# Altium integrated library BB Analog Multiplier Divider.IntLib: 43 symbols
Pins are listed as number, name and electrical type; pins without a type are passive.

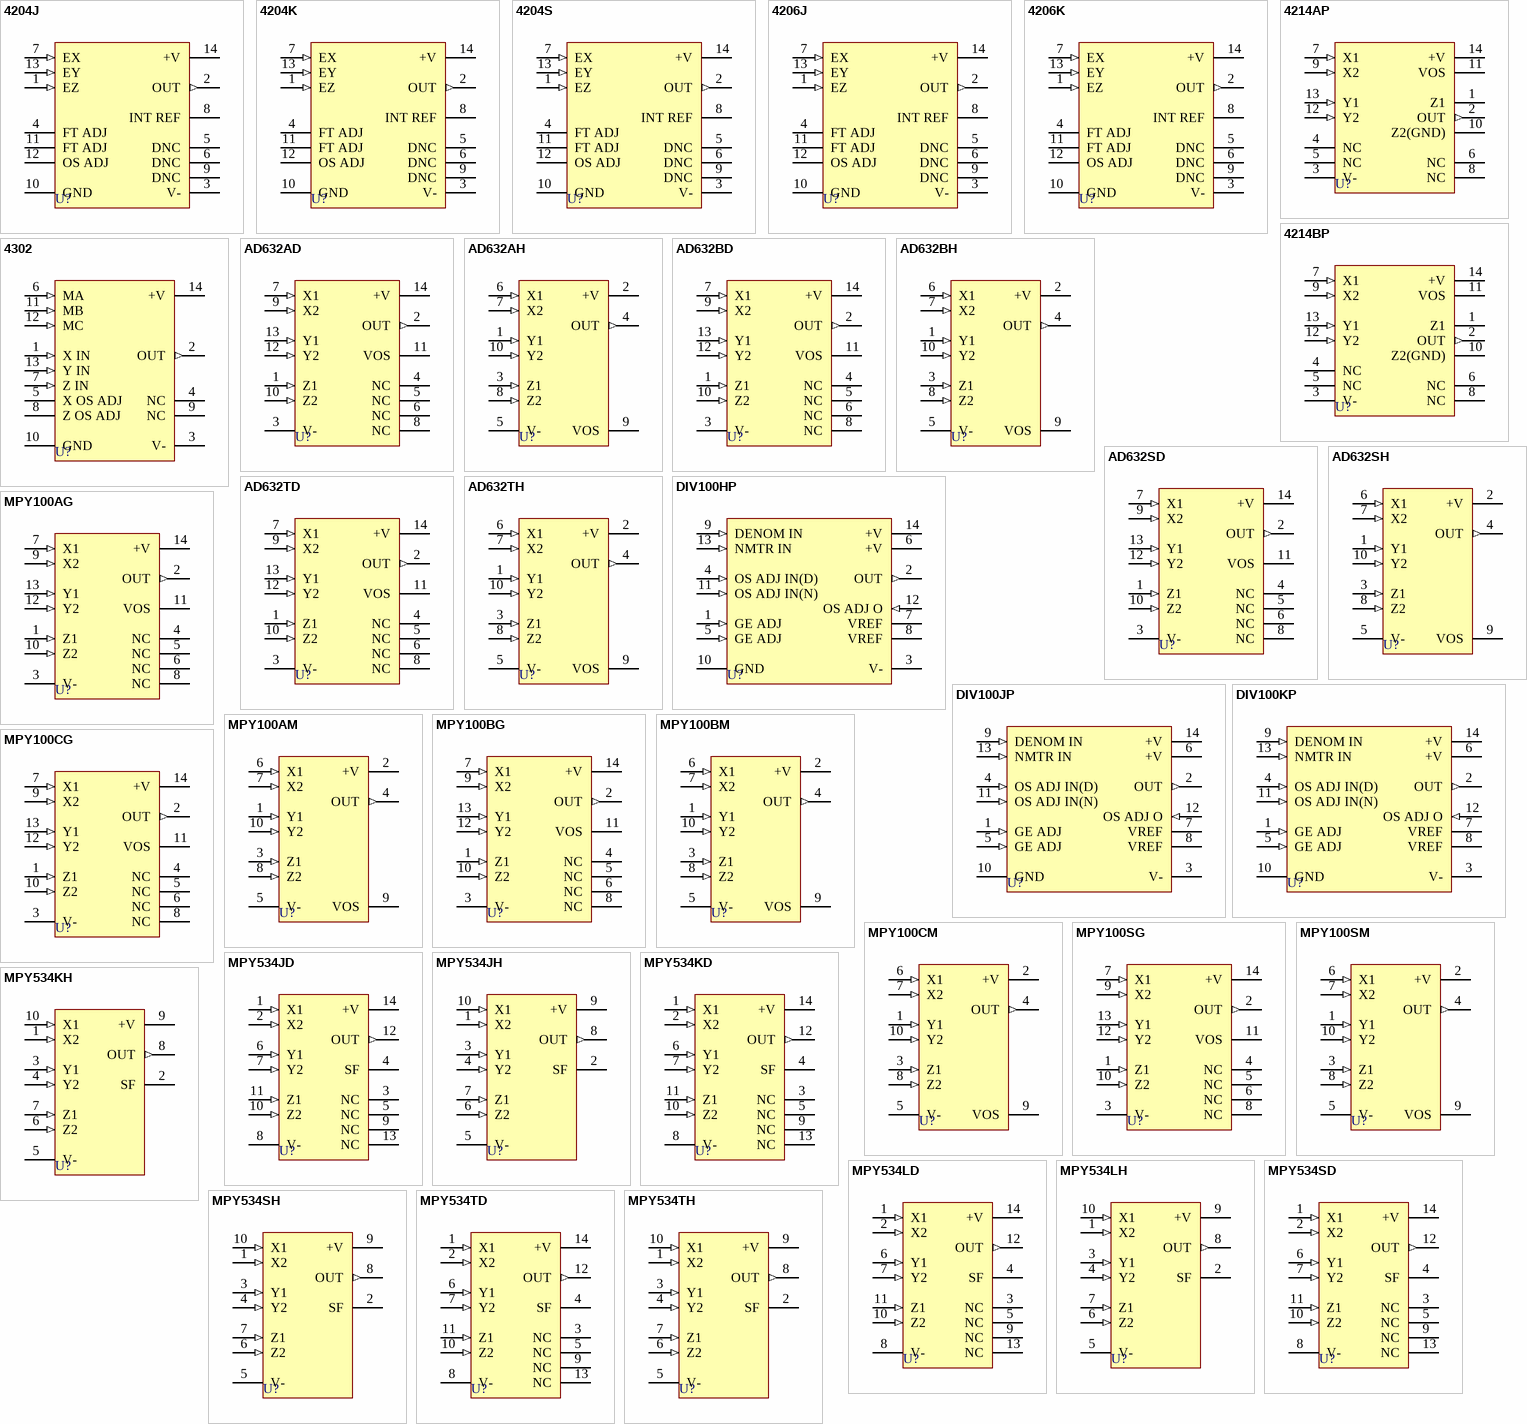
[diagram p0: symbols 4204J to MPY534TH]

## 4204J
designator U?
Analog Multiplier-Divider; Note: Make no connection to pins 5, 6 and 9
footprint ZZ107 (DIP; 14 Round Pins; Row Space 7.62 mm; Pitch 2.54 mm)
pins: 1 EZ (in), 2 OUT (out), 3 V- (power), 4 FT ADJ, 5 DNC, 6 DNC, 7 EX (in), 8 INT REF, 9 DNC, 10 GND (power), 11 FT ADJ, 12 OS ADJ, 13 EY (in), 14 +V (power)

## 4204K
designator U?
Analog Multiplier-Divider; Note: Make no connection to pins 5, 6 and 9
footprint ZZ107 (DIP; 14 Round Pins; Row Space 7.62 mm; Pitch 2.54 mm)
pins: 1 EZ (in), 2 OUT (out), 3 V- (power), 4 FT ADJ, 5 DNC, 6 DNC, 7 EX (in), 8 INT REF, 9 DNC, 10 GND (power), 11 FT ADJ, 12 OS ADJ, 13 EY (in), 14 +V (power)

## 4204S
designator U?
Analog Multiplier-Divider; Note: Make no connection to pins 5, 6 and 9
footprint ZZ107 (DIP; 14 Round Pins; Row Space 7.62 mm; Pitch 2.54 mm)
pins: 1 EZ (in), 2 OUT (out), 3 V- (power), 4 FT ADJ, 5 DNC, 6 DNC, 7 EX (in), 8 INT REF, 9 DNC, 10 GND (power), 11 FT ADJ, 12 OS ADJ, 13 EY (in), 14 +V (power)

## 4206J
designator U?
Analog Multiplier-Divider; Note: Make no connection to pins 5, 6 and 9
footprint ZZ003 (DIP; 14 Round Pins; Row Space 7.62 mm; Pitch 2.54 mm)
pins: 1 EZ (in), 2 OUT (out), 3 V- (power), 4 FT ADJ, 5 DNC, 6 DNC, 7 EX (in), 8 INT REF, 9 DNC, 10 GND (power), 11 FT ADJ, 12 OS ADJ, 13 EY (in), 14 +V (power)

## 4206K
designator U?
Analog Multiplier-Divider; Note: Make no connection to pins 5, 6 and 9
footprint ZZ003 (DIP; 14 Round Pins; Row Space 7.62 mm; Pitch 2.54 mm)
pins: 1 EZ (in), 2 OUT (out), 3 V- (power), 4 FT ADJ, 5 DNC, 6 DNC, 7 EX (in), 8 INT REF, 9 DNC, 10 GND (power), 11 FT ADJ, 12 OS ADJ, 13 EY (in), 14 +V (power)

## 4214AP
designator U?
Multiplier-Divider; Note: Pins 4, 5, 6 and 8 are No internal Connection (NC) pins.
footprint ZZ003 (DIP; 14 Round Pins; Row Space 7.62 mm; Pitch 2.54 mm)
pins: 1 Z1, 2 OUT (out), 3 V- (power), 4 NC, 5 NC, 6 NC, 7 X1 (in), 8 NC, 9 X2 (in), 10 Z2(GND), 11 VOS, 12 Y2 (in), 13 Y1 (in), 14 +V (power)

## 4214BP
designator U?
Multiplier-Divider; Note: Pins 4, 5, 6 and 8 are No internal Connection (NC) pins.
footprint ZZ003 (DIP; 14 Round Pins; Row Space 7.62 mm; Pitch 2.54 mm)
pins: 1 Z1, 2 OUT (out), 3 V- (power), 4 NC, 5 NC, 6 NC, 7 X1 (in), 8 NC, 9 X2 (in), 10 Z2(GND), 11 VOS, 12 Y2 (in), 13 Y1 (in), 14 +V (power)

## 4302
designator U?
Low-Cost Multifunction Converter; Note: Pins 4 and 9 are No internal Connection (NC) pins.
footprint ZZ003 (DIP; 14 Round Pins; Row Space 7.62 mm; Pitch 2.54 mm)
pins: 1 X IN (in), 2 OUT (out), 3 V- (power), 4 NC, 5 X OS ADJ, 6 MA (in), 7 Z IN (in), 8 Z OS ADJ, 9 NC, 10 GND (power), 11 MB (in), 12 MC (in), 13 Y IN (in), 14 +V (power)

## AD632AD
designator U?
Precision Analog Multiplier; Note: Pins 4,5,6 and 8 are No internal Connection (NC) pins.
footprint 137 (DIP; 14 Leads; Row Spacing 7.62 mm; Pitch 2.54 mm)
3D model 137 (DIP; 14 Leads; Row Spacing 7.62 mm; Pitch 2.54 mm)
pins: 1 Z1 (in), 2 OUT (out), 3 V- (power), 4 NC, 5 NC, 6 NC, 7 X1 (in), 8 NC, 9 X2 (in), 10 Z2 (in), 11 VOS, 12 Y2 (in), 13 Y1 (in), 14 +V (power)

## AD632AH
designator U?
Precision Analog Multiplier
footprint ZZ007 (Can; 10 Leads; Pin Circle Dia. 5.84 mm (TO-100); Lead Dia. 0.53 mm (max))
pins: 1 Y1 (in), 2 +V (power), 3 Z1 (in), 4 OUT (out), 5 V- (power), 6 X1 (in), 7 X2 (in), 8 Z2 (in), 9 VOS, 10 Y2 (in)

## AD632BD
designator U?
Precision Analog Multiplier; Note: Pins 4,5,6 and 8 are No internal Connection (NC) pins.
footprint 137 (DIP; 14 Leads; Row Spacing 7.62 mm; Pitch 2.54 mm)
3D model 137 (DIP; 14 Leads; Row Spacing 7.62 mm; Pitch 2.54 mm)
pins: 1 Z1 (in), 2 OUT (out), 3 V- (power), 4 NC, 5 NC, 6 NC, 7 X1 (in), 8 NC, 9 X2 (in), 10 Z2 (in), 11 VOS, 12 Y2 (in), 13 Y1 (in), 14 +V (power)

## AD632BH
designator U?
Precision Analog Multiplier
footprint ZZ007 (Can; 10 Leads; Pin Circle Dia. 5.84 mm (TO-100); Lead Dia. 0.53 mm (max))
pins: 1 Y1 (in), 2 +V (power), 3 Z1 (in), 4 OUT (out), 5 V- (power), 6 X1 (in), 7 X2 (in), 8 Z2 (in), 9 VOS, 10 Y2 (in)

## AD632SD
designator U?
Precision Analog Multiplier; Note: Pins 4,5,6 and 8 are No internal Connection (NC) pins.
footprint 137 (DIP; 14 Leads; Row Spacing 7.62 mm; Pitch 2.54 mm)
3D model 137 (DIP; 14 Leads; Row Spacing 7.62 mm; Pitch 2.54 mm)
pins: 1 Z1 (in), 2 OUT (out), 3 V- (power), 4 NC, 5 NC, 6 NC, 7 X1 (in), 8 NC, 9 X2 (in), 10 Z2 (in), 11 VOS, 12 Y2 (in), 13 Y1 (in), 14 +V (power)

## AD632SH
designator U?
Precision Analog Multiplier
footprint ZZ007 (Can; 10 Leads; Pin Circle Dia. 5.84 mm (TO-100); Lead Dia. 0.53 mm (max))
pins: 1 Y1 (in), 2 +V (power), 3 Z1 (in), 4 OUT (out), 5 V- (power), 6 X1 (in), 7 X2 (in), 8 Z2 (in), 9 VOS, 10 Y2 (in)

## AD632TD
designator U?
Precision Analog Multiplier; Note: Pins 4,5,6 and 8 are No internal Connection (NC) pins.
footprint 137 (DIP; 14 Leads; Row Spacing 7.62 mm; Pitch 2.54 mm)
3D model 137 (DIP; 14 Leads; Row Spacing 7.62 mm; Pitch 2.54 mm)
pins: 1 Z1 (in), 2 OUT (out), 3 V- (power), 4 NC, 5 NC, 6 NC, 7 X1 (in), 8 NC, 9 X2 (in), 10 Z2 (in), 11 VOS, 12 Y2 (in), 13 Y1 (in), 14 +V (power)

## AD632TH
designator U?
Precision Analog Multiplier
footprint ZZ007 (Can; 10 Leads; Pin Circle Dia. 5.84 mm (TO-100); Lead Dia. 0.53 mm (max))
pins: 1 Y1 (in), 2 +V (power), 3 Z1 (in), 4 OUT (out), 5 V- (power), 6 X1 (in), 7 X2 (in), 8 Z2 (in), 9 VOS, 10 Y2 (in)

## DIV100HP
designator U?
Analog Divider
footprint ZZ105 (DIP; 14 Round Pins; Row Space 7.62 mm; Pitch 2.54 mm)
pins: 1 GE ADJ (in), 2 OUT (out), 3 V- (power), 4 OS ADJ IN(D) (in), 5 GE ADJ (in), 6 +V (power), 7 VREF, 8 VREF, 9 DENOM IN (in), 10 GND (power), 11 OS ADJ IN(N) (in), 12 OS ADJ O (in), 13 NMTR IN (in), 14 +V (power)

## DIV100JP
designator U?
Analog Divider
footprint ZZ105 (DIP; 14 Round Pins; Row Space 7.62 mm; Pitch 2.54 mm)
pins: 1 GE ADJ (in), 2 OUT (out), 3 V- (power), 4 OS ADJ IN(D) (in), 5 GE ADJ (in), 6 +V (power), 7 VREF, 8 VREF, 9 DENOM IN (in), 10 GND (power), 11 OS ADJ IN(N) (in), 12 OS ADJ O (in), 13 NMTR IN (in), 14 +V (power)

## DIV100KP
designator U?
Analog Divider
footprint ZZ105 (DIP; 14 Round Pins; Row Space 7.62 mm; Pitch 2.54 mm)
pins: 1 GE ADJ (in), 2 OUT (out), 3 V- (power), 4 OS ADJ IN(D) (in), 5 GE ADJ (in), 6 +V (power), 7 VREF, 8 VREF, 9 DENOM IN (in), 10 GND (power), 11 OS ADJ IN(N) (in), 12 OS ADJ O (in), 13 NMTR IN (in), 14 +V (power)

## MPY100AG
designator U?
Multiplier-Divider; Note: Pins 4,5,6 and 8 are No internal Connection (NC) pins.
footprint 169F (DIP; 14 Leads; Row Spacing 7.62 mm; Pitch 2.54 mm)
3D model 010G (DIP; 14 Leads; Row Spacing 7.62 mm; Pitch 2.54 mm)
pins: 1 Z1 (in), 2 OUT (out), 3 V- (power), 4 NC, 5 NC, 6 NC, 7 X1 (in), 8 NC, 9 X2 (in), 10 Z2 (in), 11 VOS, 12 Y2 (in), 13 Y1 (in), 14 +V (power)

## MPY100AM
designator U?
Multiplier-Divider
footprint ZZ007 (Can; 10 Leads; Pin Circle Dia. 5.84 mm (TO-100); Lead Dia. 0.53 mm (max))
pins: 1 Y1 (in), 2 +V (power), 3 Z1 (in), 4 OUT (out), 5 V- (power), 6 X1 (in), 7 X2 (in), 8 Z2 (in), 9 VOS, 10 Y2 (in)

## MPY100BG
designator U?
Multiplier-Divider; Note: Pins 4,5,6 and 8 are No internal Connection (NC) pins.
footprint 169F (DIP; 14 Leads; Row Spacing 7.62 mm; Pitch 2.54 mm)
3D model 010G (DIP; 14 Leads; Row Spacing 7.62 mm; Pitch 2.54 mm)
pins: 1 Z1 (in), 2 OUT (out), 3 V- (power), 4 NC, 5 NC, 6 NC, 7 X1 (in), 8 NC, 9 X2 (in), 10 Z2 (in), 11 VOS, 12 Y2 (in), 13 Y1 (in), 14 +V (power)

## MPY100BM
designator U?
Multiplier-Divider
footprint ZZ007 (Can; 10 Leads; Pin Circle Dia. 5.84 mm (TO-100); Lead Dia. 0.53 mm (max))
pins: 1 Y1 (in), 2 +V (power), 3 Z1 (in), 4 OUT (out), 5 V- (power), 6 X1 (in), 7 X2 (in), 8 Z2 (in), 9 VOS, 10 Y2 (in)

## MPY100CG
designator U?
Multiplier-Divider; Note: Pins 4,5,6 and 8 are No internal Connection (NC) pins.
footprint 169F (DIP; 14 Leads; Row Spacing 7.62 mm; Pitch 2.54 mm)
3D model 010G (DIP; 14 Leads; Row Spacing 7.62 mm; Pitch 2.54 mm)
pins: 1 Z1 (in), 2 OUT (out), 3 V- (power), 4 NC, 5 NC, 6 NC, 7 X1 (in), 8 NC, 9 X2 (in), 10 Z2 (in), 11 VOS, 12 Y2 (in), 13 Y1 (in), 14 +V (power)

## MPY100CM
designator U?
Multiplier-Divider
footprint ZZ007 (Can; 10 Leads; Pin Circle Dia. 5.84 mm (TO-100); Lead Dia. 0.53 mm (max))
pins: 1 Y1 (in), 2 +V (power), 3 Z1 (in), 4 OUT (out), 5 V- (power), 6 X1 (in), 7 X2 (in), 8 Z2 (in), 9 VOS, 10 Y2 (in)

## MPY100SG
designator U?
Multiplier-Divider; Note: Pins 4,5,6 and 8 are No internal Connection (NC) pins.
footprint 169F (DIP; 14 Leads; Row Spacing 7.62 mm; Pitch 2.54 mm)
3D model 010G (DIP; 14 Leads; Row Spacing 7.62 mm; Pitch 2.54 mm)
pins: 1 Z1 (in), 2 OUT (out), 3 V- (power), 4 NC, 5 NC, 6 NC, 7 X1 (in), 8 NC, 9 X2 (in), 10 Z2 (in), 11 VOS, 12 Y2 (in), 13 Y1 (in), 14 +V (power)

## MPY100SM
designator U?
Multiplier-Divider
footprint ZZ007 (Can; 10 Leads; Pin Circle Dia. 5.84 mm (TO-100); Lead Dia. 0.53 mm (max))
pins: 1 Y1 (in), 2 +V (power), 3 Z1 (in), 4 OUT (out), 5 V- (power), 6 X1 (in), 7 X2 (in), 8 Z2 (in), 9 VOS, 10 Y2 (in)

## MPY534JD
designator U?
Precision Analog Multiplier; Note: Pins 3,5,9 and 13 are No internal Connection (NC) pins.
footprint 169F (DIP; 14 Leads; Row Spacing 7.62 mm; Pitch 2.54 mm)
3D model 010G (DIP; 14 Leads; Row Spacing 7.62 mm; Pitch 2.54 mm)
pins: 1 X1 (in), 2 X2 (in), 3 NC, 4 SF, 5 NC, 6 Y1 (in), 7 Y2 (in), 8 V- (power), 9 NC, 10 Z2 (in), 11 Z1 (in), 12 OUT (out), 13 NC, 14 +V (power)

## MPY534JH
designator U?
Precision Analog Multiplier
footprint ZZ007 (Can; 10 Leads; Pin Circle Dia. 5.84 mm (TO-100); Lead Dia. 0.53 mm (max))
pins: 1 X2 (in), 2 SF, 3 Y1 (in), 4 Y2 (in), 5 V- (power), 6 Z2 (in), 7 Z1 (in), 8 OUT (out), 9 +V (power), 10 X1 (in)

## MPY534KD
designator U?
Precision Analog Multiplier; Note: Pins 3,5,9 and 13 are No internal Connection (NC) pins.
footprint 169F (DIP; 14 Leads; Row Spacing 7.62 mm; Pitch 2.54 mm)
3D model 010G (DIP; 14 Leads; Row Spacing 7.62 mm; Pitch 2.54 mm)
pins: 1 X1 (in), 2 X2 (in), 3 NC, 4 SF, 5 NC, 6 Y1 (in), 7 Y2 (in), 8 V- (power), 9 NC, 10 Z2 (in), 11 Z1 (in), 12 OUT (out), 13 NC, 14 +V (power)

## MPY534KH
designator U?
Precision Analog Multiplier
footprint ZZ007 (Can; 10 Leads; Pin Circle Dia. 5.84 mm (TO-100); Lead Dia. 0.53 mm (max))
pins: 1 X2 (in), 2 SF, 3 Y1 (in), 4 Y2 (in), 5 V- (power), 6 Z2 (in), 7 Z1 (in), 8 OUT (out), 9 +V (power), 10 X1 (in)

## MPY534LD
designator U?
Precision Analog Multiplier; Note: Pins 3,5,9 and 13 are No internal Connection (NC) pins.
footprint 169F (DIP; 14 Leads; Row Spacing 7.62 mm; Pitch 2.54 mm)
3D model 010G (DIP; 14 Leads; Row Spacing 7.62 mm; Pitch 2.54 mm)
pins: 1 X1 (in), 2 X2 (in), 3 NC, 4 SF, 5 NC, 6 Y1 (in), 7 Y2 (in), 8 V- (power), 9 NC, 10 Z2 (in), 11 Z1 (in), 12 OUT (out), 13 NC, 14 +V (power)

## MPY534LH
designator U?
Precision Analog Multiplier
footprint ZZ007 (Can; 10 Leads; Pin Circle Dia. 5.84 mm (TO-100); Lead Dia. 0.53 mm (max))
pins: 1 X2 (in), 2 SF, 3 Y1 (in), 4 Y2 (in), 5 V- (power), 6 Z2 (in), 7 Z1 (in), 8 OUT (out), 9 +V (power), 10 X1 (in)

## MPY534SD
designator U?
Precision Analog Multiplier; Note: Pins 3,5,9 and 13 are No internal Connection (NC) pins.
footprint 169F (DIP; 14 Leads; Row Spacing 7.62 mm; Pitch 2.54 mm)
3D model 010G (DIP; 14 Leads; Row Spacing 7.62 mm; Pitch 2.54 mm)
pins: 1 X1 (in), 2 X2 (in), 3 NC, 4 SF, 5 NC, 6 Y1 (in), 7 Y2 (in), 8 V- (power), 9 NC, 10 Z2 (in), 11 Z1 (in), 12 OUT (out), 13 NC, 14 +V (power)

## MPY534SH
designator U?
Precision Analog Multiplier
footprint ZZ007 (Can; 10 Leads; Pin Circle Dia. 5.84 mm (TO-100); Lead Dia. 0.53 mm (max))
pins: 1 X2 (in), 2 SF, 3 Y1 (in), 4 Y2 (in), 5 V- (power), 6 Z2 (in), 7 Z1 (in), 8 OUT (out), 9 +V (power), 10 X1 (in)

## MPY534TD
designator U?
Precision Analog Multiplier; Note: Pins 3,5,9 and 13 are No internal Connection (NC) pins.
footprint 169F (DIP; 14 Leads; Row Spacing 7.62 mm; Pitch 2.54 mm)
3D model 010G (DIP; 14 Leads; Row Spacing 7.62 mm; Pitch 2.54 mm)
pins: 1 X1 (in), 2 X2 (in), 3 NC, 4 SF, 5 NC, 6 Y1 (in), 7 Y2 (in), 8 V- (power), 9 NC, 10 Z2 (in), 11 Z1 (in), 12 OUT (out), 13 NC, 14 +V (power)

## MPY534TH
designator U?
Precision Analog Multiplier
footprint ZZ007 (Can; 10 Leads; Pin Circle Dia. 5.84 mm (TO-100); Lead Dia. 0.53 mm (max))
pins: 1 X2 (in), 2 SF, 3 Y1 (in), 4 Y2 (in), 5 V- (power), 6 Z2 (in), 7 Z1 (in), 8 OUT (out), 9 +V (power), 10 X1 (in)

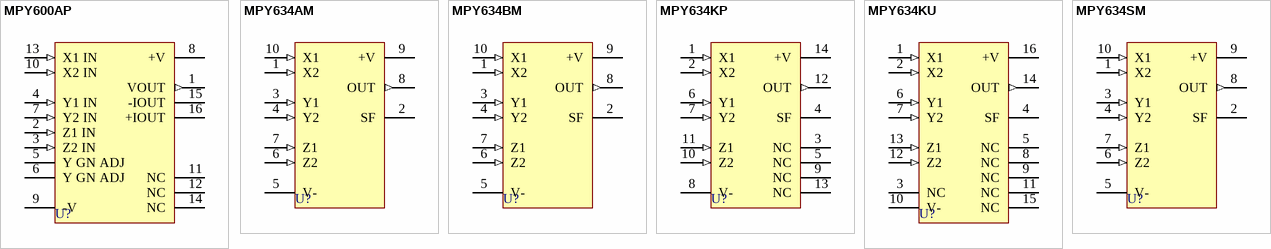
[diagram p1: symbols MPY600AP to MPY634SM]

## MPY600AP
designator U?
Wide-Bandwidth Signal Multiplier; Note: Pins 11, 12 and 14 are No internal Connection (NC) pins.
footprint ZZ180 (DIP, Plastic; 16 Leads; Row Spacing 7.62 mm; Pitch 2.54 mm)
3D model ZZ180 (DIP, Plastic; 16 Leads; Row Spacing 7.62 mm; Pitch 2.54 mm)
pins: 1 VOUT (out), 2 Z1 IN (in), 3 Z2 IN (in), 4 Y1 IN (in), 5 Y GN ADJ, 6 Y GN ADJ, 7 Y2 IN (in), 8 +V (power), 9 -V (power), 10 X2 IN (in), 11 NC, 12 NC, 13 X1 IN (in), 14 NC, 15 -IOUT, 16 +IOUT

## MPY634AM
designator U?
Wide-Bandwidth Precision Analog Multiplier
footprint ZZ007 (Can; 10 Leads; Pin Circle Dia. 5.84 mm (TO-100); Lead Dia. 0.53 mm (max))
pins: 1 X2 (in), 2 SF, 3 Y1 (in), 4 Y2 (in), 5 V- (power), 6 Z2 (in), 7 Z1 (in), 8 OUT (out), 9 +V (power), 10 X1 (in)

## MPY634BM
designator U?
Wide-Bandwidth Precision Analog Multiplier
footprint ZZ007 (Can; 10 Leads; Pin Circle Dia. 5.84 mm (TO-100); Lead Dia. 0.53 mm (max))
pins: 1 X2 (in), 2 SF, 3 Y1 (in), 4 Y2 (in), 5 V- (power), 6 Z2 (in), 7 Z1 (in), 8 OUT (out), 9 +V (power), 10 X1 (in)

## MPY634KP
designator U?
Wide-Bandwidth Precision Analog Multiplier; Note: Pins 3,5,9 and 13 are No internal Connection (NC) pins.
footprint 010G (DIP; 14 Leads; Row Spacing 7.62 mm; Pitch 2.54 mm)
3D model 010G (DIP; 14 Leads; Row Spacing 7.62 mm; Pitch 2.54 mm)
pins: 1 X1 (in), 2 X2 (in), 3 NC, 4 SF, 5 NC, 6 Y1 (in), 7 Y2 (in), 8 V- (power), 9 NC, 10 Z2 (in), 11 Z1 (in), 12 OUT (out), 13 NC, 14 +V (power)

## MPY634KU
designator U?
Wide-Bandwidth Precision Analog Multiplier; Note: Pins 3,5,8,9,11 and 15 are No internal Connection (NC) pins.
footprint 211F_N (SOIC, 16-Leads, Body 10.3x7.5mm, Pitch 1.27mm, IPC Medium Density)
footprint 211F_L (SOIC, 16-Leads, Body 10.3x7.5mm, Pitch 1.27mm, IPC High Density)
footprint 211F_M (SOIC, 16-Leads, Body 10.3x7.5mm, Pitch 1.27mm, IPC Low Density)
3D model SOIC16 (16-Pin Small Outline Integrated Circuit 1.27 mm Pitch)
pins: 1 X1 (in), 2 X2 (in), 3 NC, 4 SF, 5 NC, 6 Y1 (in), 7 Y2 (in), 8 NC, 9 NC, 10 V- (power), 11 NC, 12 Z2 (in), 13 Z1 (in), 14 OUT (out), 15 NC, 16 +V (power)

## MPY634SM
designator U?
Wide-Bandwidth Precision Analog Multiplier
footprint ZZ007 (Can; 10 Leads; Pin Circle Dia. 5.84 mm (TO-100); Lead Dia. 0.53 mm (max))
pins: 1 X2 (in), 2 SF, 3 Y1 (in), 4 Y2 (in), 5 V- (power), 6 Z2 (in), 7 Z1 (in), 8 OUT (out), 9 +V (power), 10 X1 (in)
